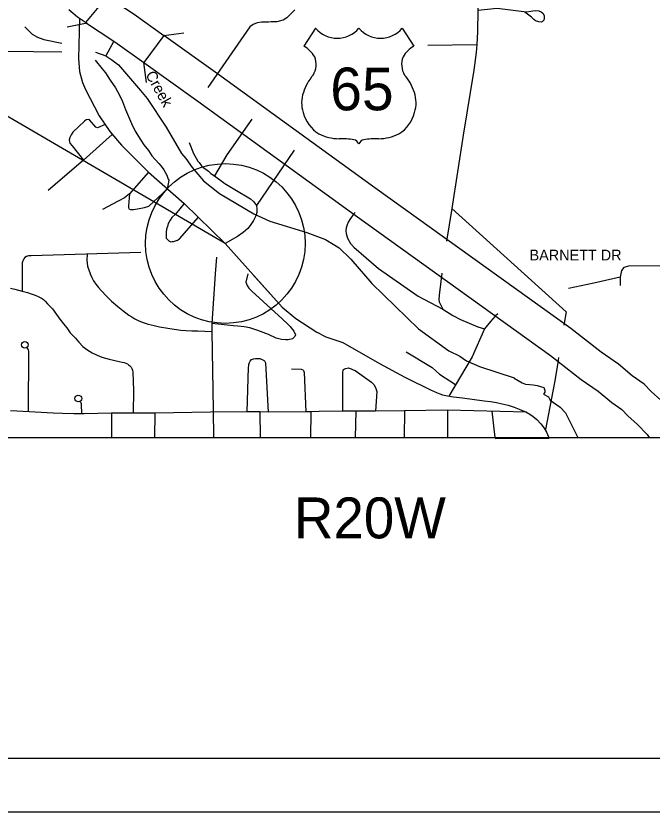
# Model space of a CAD drawing. Extents: x 19118 to 454486, y 1325406 to 1693506.
# Drawn here: x 25247 to 25720, y 1325406 to 1325997 of the extents above; entities that cross this region are included whole.
import ezdxf

# ---------------------------------------------------------------- set-up
doc = ezdxf.new("R2010")
doc.units = 0
for name, color, linetype in [('Default', 7, 'Continuous'), ('S_CURB', 7, 'Continuous'), ('S_EDGE_PAVEMENT', 7, 'Continuous'), ('S_PAVEMENT_CROWN', 7, 'Continuous'), ('S_SHOULDER', 7, 'Continuous')]:
    doc.layers.add(name, color=color, linetype=linetype)

msp = doc.modelspace()

# ---------------------------------------------------------------- linework, layer by layer
at = {"layer": 'Default'}
for p, q in [((25469.78, 1325988.01), (25461.12, 1325974.62)), ((25534.12, 1325988.01), (25542.78, 1325974.62))]:
    msp.add_line(p, q, dxfattribs=at)
for points in [[(25591.38, 1326043.83), (25590.42, 1326020.81), (25590.37, 1326001.26), (25590.13, 1325985.22), (25589.65, 1325975.89), (25589.18, 1325969.96), (25587.38, 1325956.69), (25579.38, 1325908.49), (25571.02, 1325853.97), (25567.09, 1325829.89)], [(25314.93, 1326011.67), (25298.95, 1325992.27), (25292.97, 1325996.25), (25286.44, 1326001.46)], [(25314.93, 1326011.67), (25334.96, 1325998.33), (25357.18, 1325982.47)], [(25454.49, 1326001.51), (25448.32, 1325995.55), (25445.76, 1325993.99), (25443.67, 1325993.34), (25441.08, 1325992.78), (25436.89, 1325992.59), (25434.79, 1325992.44), (25431.19, 1325992.46), (25429.69, 1325992.32), (25426.39, 1325991.95), (25423.52, 1325990.78), (25420.96, 1325988.92), (25389.69, 1325943.93)], [(25590.37, 1326001.26), (25604.74, 1326002.69), (25626.42, 1325999.97), (25629.81, 1326000.55), (25631.3, 1326000.79), (25633.2, 1326001.03), (25635.6, 1326000.78), (25637.42, 1326000.02), (25638.64, 1325999.15), (25639.58, 1325997.36), (25639.64, 1325995.06), (25639.36, 1325993.95), (25638.38, 1325992.93), (25637.49, 1325992.5), (25635.69, 1325992.56), (25633.27, 1325993.41), (25631.85, 1325994.38), (25630.1, 1325996.25), (25625.12, 1325999.94)], [(25281.2, 1325970.23), (25239.13, 1325970.66), (25237.1, 1325970.87), (25235.38, 1325971.31), (25233.33, 1325972.19), (25231.54, 1325973.39), (25229.92, 1325974.75), (25228.63, 1325976.3), (25227.53, 1325978.05), (25226.37, 1325980.06), (25225.59, 1325981.29), (25224.75, 1325982.4), (25223.18, 1325984.17), (25220.15, 1325986.65), (25209.79, 1325994.38), (25207.78, 1325995.76), (25206.04, 1325996.07), (25204.2, 1325996.03), (25196.5, 1325994.65)], [(25294.44, 1325995.08), (25293.57, 1325965.53), (25294.49, 1325955.73), (25296.57, 1325947.66), (25298.8, 1325942.3), (25309.14, 1325922.79), (25316.91, 1325911.34), (25325.54, 1325901.11), (25345.6, 1325881.12), (25372.25, 1325857.67), (25402.73, 1325828.09), (25444.92, 1325780.74), (25455.01, 1325772.45), (25470.65, 1325762.27), (25477.53, 1325758.82), (25489.93, 1325754.49)], [(25253.83, 1325989.06), (25259.19, 1325983.48), (25263.22, 1325981.21), (25267.89, 1325979.47), (25281.39, 1325976.79)], [(25300.01, 1325991.56), (25285.31, 1325988.61)], [(25298.95, 1325992.27), (25320.77, 1325977.74), (25342.18, 1325962.47)], [(25747.3, 1325684.11), (25741.92, 1325693.24), (25735.2, 1325702.36), (25726.27, 1325711.78), (25719.03, 1325718.12), (25713.76, 1325723.71), (25705.01, 1325729.87), (25694.78, 1325738.39), (25681.91, 1325747.34), (25659.38, 1325764.91), (25513.88, 1325869.3), (25396.99, 1325954.08), (25357.18, 1325982.47), (25342.18, 1325962.47)], [(25357.18, 1325982.47), (25372.03, 1325984.59)], [(25319.93, 1325978.35), (25314.05, 1325967.41)], [(25553.24, 1325975.27), (25589.65, 1325975.89)], [(25306.2, 1325970.03), (25314.05, 1325967.41), (25318.39, 1325964.57), (25323.36, 1325960.7), (25339.62, 1325941.72), (25344.66, 1325935.82), (25358.88, 1325914.56), (25370.22, 1325894.89), (25373.36, 1325891.31), (25378.22, 1325884.6), (25386.55, 1325874.57), (25398.47, 1325865.31), (25423.83, 1325850.15), (25435.86, 1325844.7), (25463.26, 1325836.3), (25477.19, 1325831.1), (25487.34, 1325824.82), (25495.93, 1325816.49), (25511.65, 1325798.4), (25546.14, 1325764.69), (25568.72, 1325748.46), (25577.02, 1325744.54), (25581.8, 1325740.94), (25591.61, 1325736.65), (25617.34, 1325728.33)], [(25306.04, 1325964.32), (25311.21, 1325957.77), (25313.68, 1325954.72), (25317.31, 1325949.29), (25321.14, 1325943.66), (25324.26, 1325938.32), (25326.37, 1325933.56), (25328.71, 1325927.69), (25333.05, 1325917.17), (25335.88, 1325911.42), (25340.04, 1325904.69), (25342.21, 1325901.43), (25345.61, 1325897.1), (25348.2, 1325893.25), (25353.24, 1325887.55), (25354.98, 1325885.48), (25356.95, 1325882.82), (25359.24, 1325878.76), (25360.31, 1325875.88), (25360.73, 1325874.99), (25359.6, 1325868.51)], [(25344.29, 1325947.62), (25342.18, 1325962.47)], [(25342.18, 1325962.47), (25382.39, 1325933.78), (25499.25, 1325849.03), (25644.4, 1325744.89), (25667.08, 1325727.2), (25679.62, 1325718.48), (25689.79, 1325710.02), (25697.3, 1325704.72), (25701.67, 1325700.1), (25708.92, 1325693.74), (25715.99, 1325686.28), (25717.59, 1325684.11)], [(25313.39, 1325916.37), (25307.81, 1325913.89), (25306.5, 1325914.56), (25301.77, 1325919.87), (25300.87, 1325920.05), (25299.47, 1325919.82), (25298.19, 1325918.89), (25289.38, 1325910.67), (25288.22, 1325908.74), (25287.16, 1325906.71), (25286.7, 1325905.09), (25287.36, 1325902.6), (25289.01, 1325900.53), (25297.35, 1325890)], [(25422.44, 1325920.31), (25403.92, 1325893.8), (25394.67, 1325878.36)], [(25318.76, 1325909.08), (25297.35, 1325890), (25271.15, 1325867.35)], [(25376, 1325903), (25379.08, 1325894.85), (25381.06, 1325891.48), (25382.41, 1325889.31), (25383.24, 1325888.13), (25384.99, 1325885.86), (25386.22, 1325884.58), (25388.35, 1325883.23), (25390.19, 1325881.67), (25392.03, 1325880), (25394.67, 1325878.36), (25402.4, 1325872.62), (25409.71, 1325868.17), (25421.37, 1325861.22), (25423.62, 1325859.36), (25425.79, 1325856.31), (25426.24, 1325853.81), (25426.2, 1325851.2), (25425.46, 1325848.58), (25423.74, 1325845.23), (25421.22, 1325841.47), (25419.37, 1325839.32), (25415.94, 1325836.34), (25411.81, 1325833.23), (25402.73, 1325828.09)], [(25453.88, 1325897.27), (25425.79, 1325856.31)], [(25345.6, 1325881.12), (25331.54, 1325864.9), (25327.81, 1325861.91), (25323.26, 1325859.61), (25311.49, 1325853.43)], [(25331.54, 1325864.9), (25331.17, 1325859.08), (25330.74, 1325856.07), (25330.77, 1325854.86), (25331.09, 1325853.87), (25332.3, 1325853.39), (25334.51, 1325853.34), (25337.5, 1325853.71), (25342.78, 1325854.73), (25345.85, 1325855.91), (25359.6, 1325868.51)], [(25372.25, 1325857.67), (25365.8, 1325849.94), (25362.96, 1325847.27), (25361.7, 1325845.34), (25360.74, 1325843.61), (25360.36, 1325843), (25359.71, 1325840.78), (25359.15, 1325838.66), (25358.9, 1325836.55), (25358.85, 1325834.35), (25358.79, 1325832.84), (25358.91, 1325832.04), (25360.85, 1325829.98), (25361.26, 1325829.79), (25362.27, 1325829.41), (25363.37, 1325829.44), (25364.36, 1325829.66), (25365.86, 1325829.99), (25367.24, 1325830.63), (25368.62, 1325831.56), (25382.88, 1325847.69)], [(25571.02, 1325853.97), (25656.01, 1325777.3), (25654.18, 1325767.37)], [(25499.12, 1325851.16), (25497.87, 1325849.81), (25495.26, 1325845.95), (25494.11, 1325843.81), (25493.25, 1325841.99), (25492.6, 1325839.67), (25492.36, 1325837.36), (25492.5, 1325835.46), (25493.48, 1325831.97), (25495.77, 1325828.01), (25498.13, 1325825.36), (25516.6, 1325809.54), (25546.09, 1325789.05), (25564.42, 1325779.24), (25571.83, 1325774.5), (25577.4, 1325771.71), (25590.43, 1325766.09), (25595.16, 1325764.8)], [(25339.89, 1325821.34), (25258.4, 1325818.99), (25256.53, 1325818.84), (25255.07, 1325818.4), (25253.9, 1325817.67), (25253.13, 1325816.64), (25252.36, 1325815.24), (25251.95, 1325813.7), (25251.77, 1325811.64), (25251.83, 1325805.55)], [(25300.04, 1325820.19), (25299.97, 1325815.74), (25300.15, 1325813.48), (25300.46, 1325811.35), (25300.79, 1325809.76), (25301.24, 1325808.41), (25302.23, 1325805.69), (25302.29, 1325805.55)], [(25396.13, 1325817.94), (25395.26, 1325805.55)], [(25732.93, 1325811.52), (25702.19, 1325811.29), (25698.89, 1325810.22), (25697.03, 1325808.1), (25696.05, 1325803.06), (25696.09, 1325796.85)], [(25251.83, 1325805.55), (25251.95, 1325792.74)], [(25302.29, 1325805.55), (25303.5, 1325802.88), (25304.85, 1325800.43), (25306.57, 1325797.89), (25308.56, 1325795.45), (25310.63, 1325793.18), (25314.52, 1325789.02), (25318.31, 1325785.3), (25322.92, 1325781.31), (25326.54, 1325778.32), (25331.14, 1325774.97), (25333.4, 1325773.52), (25335.64, 1325772.25), (25338.55, 1325770.71), (25341.79, 1325769.31), (25345.42, 1325768.18), (25349.84, 1325767.09), (25353.73, 1325766.27), (25360.05, 1325765.19), (25364.75, 1325764.46), (25369.72, 1325763.83), (25373.6, 1325763.56), (25377.85, 1325763.28), (25382.28, 1325763.19), (25392.74, 1325762.79)], [(25419.35, 1325805.55), (25417.88, 1325799.39), (25418.94, 1325796.81), (25420.28, 1325794.93), (25422.44, 1325792.78), (25444.92, 1325772.03), (25449.42, 1325767.92), (25450.95, 1325766.55), (25453.63, 1325763.11), (25454.89, 1325760.33), (25454.32, 1325758.91), (25452.66, 1325757.37), (25449.37, 1325756.59), (25447.58, 1325756.45), (25444.37, 1325756.78), (25440.64, 1325757.8), (25434.88, 1325760.48), (25426.8, 1325763.6), (25420.85, 1325765.57), (25416.64, 1325766.28), (25412.02, 1325766.78), (25408.92, 1325767.01), (25392.67, 1325768.65)], [(25395.26, 1325805.55), (25392.67, 1325768.65), (25392.74, 1325762.79)], [(25422.81, 1325805.55), (25444.92, 1325780.74), (25455.01, 1325772.45), (25470.65, 1325762.27), (25472.37, 1325761.41)], [(25563.64, 1325806.16), (25561.58, 1325789.8), (25561.35, 1325786.49), (25561.69, 1325784.79), (25564.42, 1325779.24)], [(25696.05, 1325803.06), (25676.6, 1325798.53), (25657.59, 1325794.6)], [(25243.09, 1325795.01), (25246.27, 1325794.27), (25251.93, 1325792.75), (25255.77, 1325791.65), (25258.52, 1325790.71), (25261.42, 1325789.69), (25263.74, 1325788.75), (25264.83, 1325788.24), (25266.28, 1325787.37), (25267.58, 1325786.42), (25268.89, 1325785.33), (25270.77, 1325783.34)], [(25270.77, 1325783.34), (25274.36, 1325779.61), (25277.26, 1325775.36), (25279.84, 1325771.91), (25282.42, 1325768.46), (25284.99, 1325765.41), (25287.47, 1325761.86), (25291.36, 1325757.74), (25293.93, 1325754.79), (25296.81, 1325751.65), (25299.86, 1325749.31), (25303.82, 1325746.99)], [(25605.29, 1325775.83), (25603.25, 1325774.2), (25599.74, 1325770.21), (25595.16, 1325764.8), (25586.04, 1325743.94), (25568.76, 1325714.81)], [(25392.74, 1325762.79), (25393.71, 1325704.64), (25393.88, 1325684.11)], [(25489.93, 1325754.49), (25517.31, 1325739.05), (25536.08, 1325728.85), (25543.05, 1325725.32), (25549.63, 1325722.05), (25555.17, 1325719.44), (25559.73, 1325717.35), (25562.08, 1325716.43), (25564.16, 1325715.78), (25567.81, 1325715), (25572.24, 1325714.34), (25579.02, 1325713.43), (25594.92, 1325711.34), (25599.61, 1325710.68), (25604.17, 1325709.9), (25608.47, 1325708.98), (25612.78, 1325707.94), (25617.34, 1325706.5), (25622.29, 1325704.67), (25624.11, 1325703.89), (25626.07, 1325702.97), (25628.94, 1325701.27), (25631.45, 1325699.55), (25634.15, 1325697.35), (25637.17, 1325694.17), (25639.49, 1325691.08), (25641.45, 1325687.94), (25642.75, 1325684.54), (25642.82, 1325684.11)], [(25255.2, 1325750.74), (25255.75, 1325749.93), (25256.21, 1325749.12), (25256.5, 1325748.2), (25256.23, 1325703.28)], [(25303.82, 1325746.99), (25307.5, 1325745.08), (25310.9, 1325743.7), (25313.66, 1325742.87), (25316.55, 1325742.13), (25323.86, 1325740.47), (25326.08, 1325740.01), (25327.6, 1325739.6), (25328.82, 1325739.18), (25329.99, 1325738.67), (25330.93, 1325738.08), (25331.51, 1325737.61), (25332.06, 1325737.06), (25332.79, 1325736.19), (25333.3, 1325735.31), (25333.71, 1325733.98), (25333.99, 1325732.45), (25334.56, 1325718.91), (25334.37, 1325702.14)], [(25537.12, 1325747.75), (25556.3, 1325736.05), (25561.92, 1325730.97), (25573.8, 1325723.32)], [(25419.08, 1325702.98), (25420.03, 1325735.98), (25420.19, 1325737.59), (25420.18, 1325738.29), (25420.64, 1325739.81), (25421.12, 1325740.72), (25422.19, 1325741.95), (25423.68, 1325742.48), (25425.08, 1325742.81), (25428.28, 1325742.69), (25430.1, 1325742.02), (25431.82, 1325740.86), (25432.65, 1325739.58), (25434.5, 1325702.73)], [(25650.29, 1325743.33), (25649.77, 1325739.57), (25647.31, 1325724.77), (25640.7, 1325689.89)], [(25451.87, 1325735.1), (25459.18, 1325734.76), (25460.29, 1325734.39), (25460.8, 1325733.8), (25461.33, 1325732.4), (25462.5, 1325703.16)], [(25490.01, 1325703.48), (25490.05, 1325732.35), (25490.31, 1325733.86), (25490.5, 1325734.47), (25490.99, 1325734.88), (25491.39, 1325734.99), (25491.59, 1325734.99), (25492.38, 1325735.31), (25493.38, 1325735.63), (25494.18, 1325735.65), (25494.78, 1325735.47), (25496.19, 1325735.1), (25497.81, 1325734.23), (25499.12, 1325733.66), (25511.23, 1325725.01), (25513.07, 1325723.35), (25514.22, 1325721.17), (25514.75, 1325719.58), (25515.18, 1325718.28), (25514.42, 1325703.53)], [(25617.41, 1325728.31), (25617.28, 1325728.17), (25623.19, 1325724.62), (25625.84, 1325723.73), (25628.79, 1325723.43), (25631.45, 1325723.14), (25634.4, 1325722.54), (25636.76, 1325721.95), (25639.42, 1325721.06), (25640.01, 1325718.99), (25640.01, 1325717.81), (25639.12, 1325716.33), (25642.75, 1325714.12), (25643.93, 1325711.75), (25651.59, 1325706.61), (25655.43, 1325702.47), (25664.6, 1325684.11)], [(25294.78, 1325710.86), (25295.3, 1325709.93), (25295.58, 1325709.28), (25295.78, 1325708.56), (25295.95, 1325701.87)], [(25243.09, 1325704.07), (25256.92, 1325703.25), (25274.8, 1325702.36), (25281.89, 1325702.02), (25290.27, 1325701.93), (25297.87, 1325701.85), (25318.08, 1325702.31)], [(25472.37, 1325703.23), (25466.2, 1325703.14), (25462.5, 1325703.16), (25434.5, 1325702.73), (25428.28, 1325703.19), (25419.08, 1325702.98), (25391.77, 1325702.87), (25350.27, 1325702.22), (25342.71, 1325702.22), (25333.26, 1325702.15), (25318.08, 1325702.2)], [(25318.08, 1325702.31), (25318.08, 1325684.11)], [(25350.27, 1325702.22), (25350.11, 1325684.11)], [(25428.28, 1325703.19), (25428.55, 1325684.11)], [(25466.2, 1325703.14), (25466.08, 1325684.11)], [(25626.47, 1325702.88), (25567.73, 1325704.23), (25535.82, 1325703.81), (25514.42, 1325703.53), (25499.61, 1325703.5), (25490.01, 1325703.48), (25472.37, 1325703.23)], [(25499.61, 1325703.5), (25499.3, 1325684.11)], [(25535.82, 1325703.81), (25535.59, 1325684.11)], [(25567.73, 1325704.23), (25567.85, 1325684.11)], [(25600.67, 1325703.47), (25603.04, 1325684.11)], [(25603.13, 1325683.38), (25643.4, 1325683.6)]]:
    msp.add_lwpolyline(points, dxfattribs=at)
for centre in [(25253.8, 1325752.81), (25293.55, 1325713.04)]:
    msp.add_circle(centre, 2.5, dxfattribs=at)
for centre, radius, start, end in [((25485.89, 1326001.57), 21.06, 220.07504, 319.67012), ((25518.01, 1326001.57), 21.06, 220.32988, 319.92496), ((25449.82, 1325955.19), 22.48, 30.7809, 59.98827), ((25554.09, 1325955.19), 22.48, 120.01173, 149.2191), ((25454.76, 1325961.12), 15.41, 328.81046, 21.21077), ((25549.14, 1325961.12), 15.41, 158.78923, 211.18954), ((25495.07, 1325929.53), 35.96, 138.95648, 162.69135), ((25508.83, 1325929.53), 35.96, 17.30865, 41.04352), ((25483.2, 1325932.48), 23.76, 160.95764, 197.38186), ((25520.7, 1325932.48), 23.76, 342.61814, 19.04236), ((25487.07, 1325932.54), 27.49, 195.10743, 237.13119), ((25516.84, 1325932.54), 27.49, 302.86881, 344.89257), ((25487.58, 1325941.2), 35.3, 244.07708, 269.57785), ((25488.39, 1325841.24), 64.67, 81.19416, 90.95387), ((25515.51, 1325841.24), 64.67, 89.04613, 98.80584), ((25516.32, 1325941.2), 35.3, 270.42215, 295.92292), ((25496.48, 1325899.22), 6.2, 28.03422, 72.98637), ((25507.42, 1325899.22), 6.2, 107.01363, 151.96578)]:
    msp.add_arc(centre, radius, start, end, dxfattribs=at)
at = {"layer": 'S_CURB'}
msp.add_lwpolyline([(26142.72, 1326309.74), (24887.1, 1326309.74), (24887.1, 1325684.11), (26142.72, 1325684.11)], close=True, dxfattribs=at)
at = {"layer": 'S_EDGE_PAVEMENT'}
msp.add_lwpolyline([(23759.74, 1327539.29), (27093.14, 1327539.29), (27093.14, 1325405.92), (23759.74, 1325405.92)], close=True, dxfattribs=at)
at = {"layer": 'S_PAVEMENT_CROWN'}
msp.add_lwpolyline([(25402.73, 1325828.09), (24751.06, 1326208.5)], dxfattribs=at)
msp.add_circle((25402.73, 1325828.09), 59.31, dxfattribs=at)
at = {"layer": 'S_SHOULDER'}
msp.add_line((27045.61, 1325445.75), (23883.81, 1325445.75), dxfattribs=at)

# ---------------------------------------------------------------- texts
at = {"layer": 'Default'}
for s, height, p in [('65', 31.68, (25480.68, 1325926.99)), ('BARNETT DR', 8, (25628.75, 1325815.48))]:
    msp.add_text(s, height=height, dxfattribs=at).set_placement(p)
msp.add_text('Creek', height=8, rotation=299.12198, dxfattribs=at).set_placement((25343.19, 1325953.5))
at = {"layer": 'S_CURB'}
msp.add_text('R20W', height=30.36, dxfattribs=at).set_placement((25453.75, 1325609.17))

doc.saveas('drawing.dxf')
